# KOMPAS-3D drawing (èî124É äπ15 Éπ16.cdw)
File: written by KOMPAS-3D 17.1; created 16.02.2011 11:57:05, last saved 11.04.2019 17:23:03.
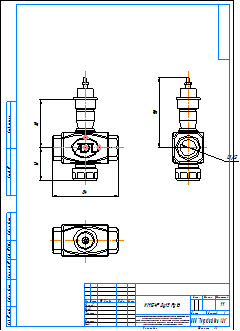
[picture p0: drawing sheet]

Title block, sheet 1: name: КМ124Р Ду15 Ру16; material: Внимание! Данный продукт является объектом авторского права ООО «Торговый Дом АДЛ». / Запрещается изменение, копирование, распространение / (в том числе путем копирования на другие сайты и ресурсы в Интернете) / или любое иное использование информации и объектов без предварительного / согласия правообладателя (ООО «Торговый Дом АДЛ»).; scale: 1:1; sheets: 1; organisation: ООО "Торговый дом АДЛ"; sheet format: A3; stored path: \\adlc.lan\data\АДЛ_ПКД\3D-модели\ADL production\Клапаны ГРАНРЕГ\Двухходовой клапан KM124P\KOMPAS 2D\КМ124Р Ду15 Ру16.cdw

Views: Спереди 1, Проекционный вид 2, Проекционный вид 3, Спереди 4, Проекционный вид 5, Проекционный вид 6
Dimensions and other numbers on the sheet: 84; 61; 41; 90; 1:1; 1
